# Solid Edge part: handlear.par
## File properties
Author: Deepak Maini
Template: Normal.par
Last saved by: Robert a Rhodes jr
Revision: 8
Application: Solid Edge
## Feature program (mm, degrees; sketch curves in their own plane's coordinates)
sketch for "unnamed RevolvedProtrusion 1" plane through (0, 0, 0) normal (0, -1, 0) x-axis (1, 0, 0)
  arc centre (0, 0) radius 18 from (0, 18) to (0, -18) cw
  line (0, 18) -> (0, -18)
revolve "unnamed RevolvedProtrusion 1" add full turn 360 deg
sketch for "unnamed RevolvedProtrusion 2" plane through (0, 0, 0) normal (0, -1, 0) x-axis (1, 0, 0)
  arc centre (0, -45) radius 15 from (0, -30) to (0, -60) cw
  line (0, -59.9184) -> (0, -30)
revolve "unnamed RevolvedProtrusion 2" add finite 360 deg about sketch line (0, -32.5584) -> (0, -81.2592)
sketch for "unnamed RevolvedProtrusion 3" plane through (0, 0, 0) normal (0, -1, 0) x-axis (1, 0, 0)
  arc centre (0, -100) radius 13 from (0, -87) to (0, -113) cw
  line (0, -113) -> (0, -87)
revolve "unnamed RevolvedProtrusion 3" add finite 360 deg about sketch line (0, -73.5984) -> (0, -117.648)
sketch for "unnamed Protrusion 1" plane through (0, 0, -10) normal (0, 0, 1) x-axis (1, 0, 0)
  circle centre (0, 0) radius 12
extrude "unnamed Protrusion 1" add finite 88.9 along -normal
sketch for "unnamed Cutout 1" #1 plane through (0, 0, 0) normal (0, -1, 0) x-axis (1, 0, 0)
  line (-12, -34.1892) -> (-12, -60.2724)
  line (-12, -60.2724) -> (-20.6588, -60.2724)
  line (-20.6588, -60.2724) -> (-20.6588, -34.1892)
  line (-20.6588, -34.1892) -> (-12, -34.1892)
sketch for "unnamed Cutout 1" #2 plane through (0, 0, 0) normal (0, -1, 0) x-axis (1, 0, 0)
  line (10, -88.7383) -> (10, -115.4592)
  line (10, -115.4592) -> (20.9304, -115.4592)
  line (20.9304, -115.4592) -> (20.9304, -88.7383)
  line (20.9304, -88.7383) -> (10, -88.7383)
sketch for "unnamed Cutout 1" #3 plane through (0, 0, 0) normal (0, -1, 0) x-axis (1, 0, 0)
  line (12, -34.1088) -> (12, -60.192)
  line (12, -60.192) -> (21.7512, -60.192)
  line (21.7512, -60.192) -> (21.7512, -34.1088)
  line (21.7512, -34.1088) -> (12, -34.1088)
extrude "unnamed Cutout 1" cut finite 152.4 symmetric
sketch for "unnamed Hole 1" plane through (12, 0, -45) normal (1, 0, 0) x-axis (0, 0, -1)
  hole centre (0, 0) bore radius 6.5
hole "unnamed Hole 1" through
sketch for "unnamed Hole 2" plane through (10, 0, -100) normal (1, 0, 0) x-axis (0, 0, -1)
  hole centre (0, 0) bore radius 5
hole "unnamed Hole 2" finite
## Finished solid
Body 1: solid body, 11 faces, 11 edges, 1 vertex.
  Faces by surface: cone 3, plane 3, sphere 3, cylinder 2
  Edges by curve: circle 11
Bounding box of the edges (mm; curved faces can reach further): 24.000 x 23.491 x 94.667, from (-12, -11.7455, -108.3066) to (12, 11.7455, -13.6398).
Cylindrical faces by radius (mm): R5 x1, R6.5 x1
Conical faces (half-angle, radius in mm at the cone's reference point): 4 deg R12 x2, 59 deg R5 x1
Spherical faces by radius (mm): R13 x1, R15 x1, R18 x1
Planar faces by outward normal: +x 2, -x 1
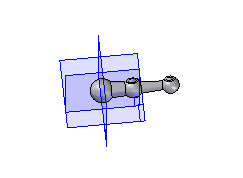
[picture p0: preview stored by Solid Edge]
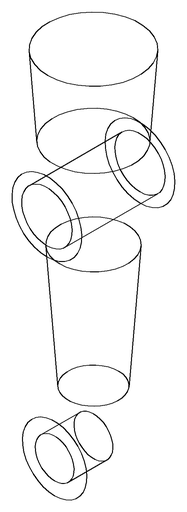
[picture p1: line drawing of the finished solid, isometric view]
